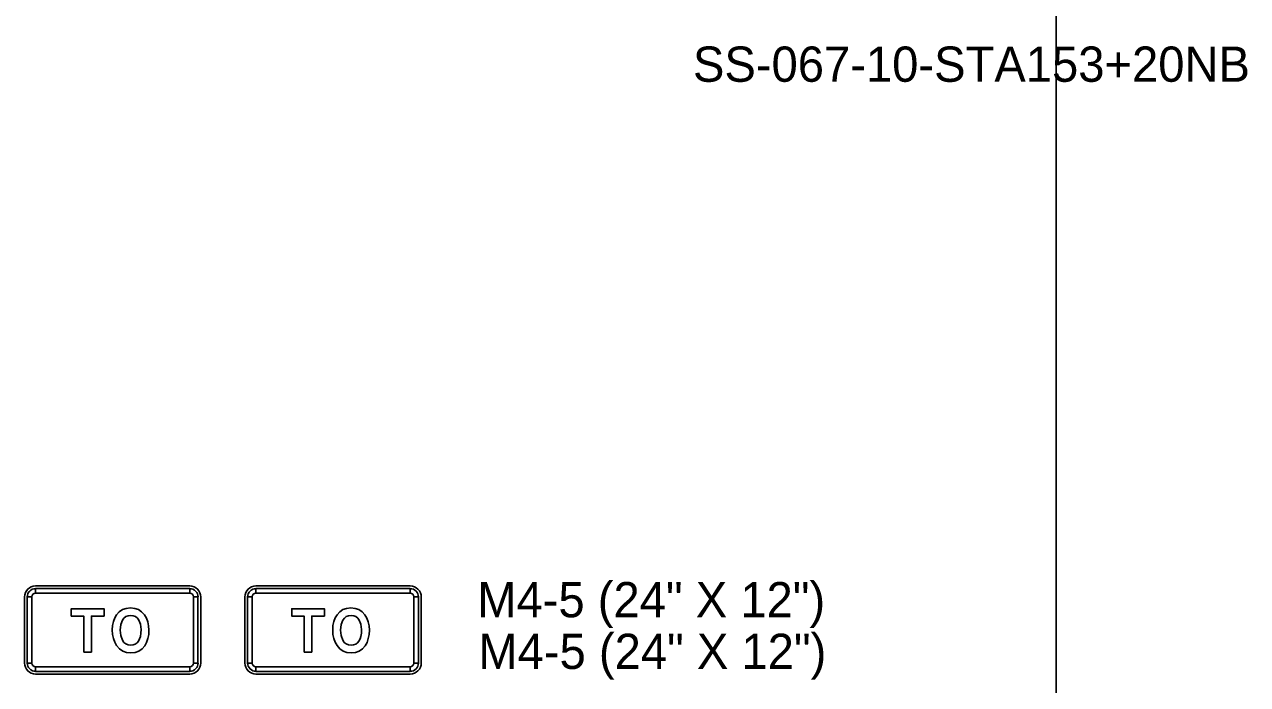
# Model space of a CAD drawing. Extents: x 1001568 to 1002149, y 1840825 to 1841423.
# Drawn here: x 1001938.95 to 1001952.82, y 1841187.33 to 1841194.82 of the extents above; entities that cross this region are included whole.
import ezdxf

# ---------------------------------------------------------------- set-up
doc = ezdxf.new("R2010")
doc.units = 0
for name, color, linetype in [('40', 7, 'Continuous'), ('R_No Plot', 7, 'Continuous'), ('SIGNS', 7, 'Continuous')]:
    doc.layers.add(name, color=color, linetype=linetype)

msp = doc.modelspace()

# ---------------------------------------------------------------- linework, layer by layer
at = {"layer": 'R_No Plot'}
msp.add_line((1001950.65, 1841210.667), (1001950.65, 1841148.127), dxfattribs=at)
at = {"layer": 'SIGNS'}
for p, q in [((1001940.823, 1841188.451), (1001939.073, 1841188.451)), ((1001943.323, 1841188.451), (1001941.573, 1841188.451)), ((1001938.948, 1841188.326), (1001938.948, 1841187.576)), ((1001938.979, 1841188.326), (1001939.031, 1841188.326)), ((1001939.073, 1841188.368), (1001939.073, 1841188.42)), ((1001940.823, 1841188.42), (1001940.823, 1841188.368)), ((1001940.864, 1841188.326), (1001940.916, 1841188.326)), ((1001940.948, 1841187.576), (1001940.948, 1841188.326)), ((1001941.448, 1841188.326), (1001941.448, 1841187.576)), ((1001941.479, 1841188.326), (1001941.531, 1841188.326)), ((1001941.573, 1841188.368), (1001941.573, 1841188.42)), ((1001943.323, 1841188.42), (1001943.323, 1841188.368)), ((1001943.364, 1841188.326), (1001943.416, 1841188.326)), ((1001943.448, 1841187.576), (1001943.448, 1841188.326)), ((1001939.031, 1841187.576), (1001938.979, 1841187.576)), ((1001939.073, 1841187.482), (1001939.073, 1841187.534)), ((1001940.823, 1841187.534), (1001940.823, 1841187.482)), ((1001940.916, 1841187.576), (1001940.864, 1841187.576)), ((1001941.531, 1841187.576), (1001941.479, 1841187.576)), ((1001941.573, 1841187.482), (1001941.573, 1841187.534)), ((1001943.323, 1841187.534), (1001943.323, 1841187.482)), ((1001943.416, 1841187.576), (1001943.364, 1841187.576)), ((1001939.073, 1841187.451), (1001940.823, 1841187.451)), ((1001941.573, 1841187.451), (1001943.323, 1841187.451))]:
    msp.add_line(p, q, dxfattribs=at)
for points in [[(1001938.979, 1841188.326), (1001938.979, 1841187.576), (1001939.031, 1841187.576), (1001939.031, 1841188.326), (1001938.979, 1841188.326), (1001938.979, 1841188.326)], [(1001940.823, 1841188.42), (1001939.073, 1841188.42), (1001939.073, 1841188.368), (1001940.823, 1841188.368), (1001940.823, 1841188.42), (1001940.823, 1841188.42)], [(1001940.916, 1841187.576), (1001940.916, 1841188.326), (1001940.864, 1841188.326), (1001940.864, 1841187.576), (1001940.916, 1841187.576), (1001940.916, 1841187.576)], [(1001941.479, 1841188.326), (1001941.479, 1841187.576), (1001941.531, 1841187.576), (1001941.531, 1841188.326), (1001941.479, 1841188.326), (1001941.479, 1841188.326)], [(1001943.323, 1841188.42), (1001941.573, 1841188.42), (1001941.573, 1841188.368), (1001943.323, 1841188.368), (1001943.323, 1841188.42), (1001943.323, 1841188.42)], [(1001943.416, 1841187.576), (1001943.416, 1841188.326), (1001943.364, 1841188.326), (1001943.364, 1841187.576), (1001943.416, 1841187.576), (1001943.416, 1841187.576)], [(1001939.62, 1841187.701), (1001939.707, 1841187.701), (1001939.707, 1841188.109), (1001939.85, 1841188.109), (1001939.85, 1841188.192), (1001939.479, 1841188.192), (1001939.479, 1841188.109), (1001939.62, 1841188.109)], [(1001942.12, 1841187.701), (1001942.207, 1841187.701), (1001942.207, 1841188.109), (1001942.35, 1841188.109), (1001942.35, 1841188.192), (1001941.979, 1841188.192), (1001941.979, 1841188.109), (1001942.12, 1841188.109)], [(1001939.073, 1841187.482), (1001940.823, 1841187.482), (1001940.823, 1841187.534), (1001939.073, 1841187.534), (1001939.073, 1841187.482), (1001939.073, 1841187.482)], [(1001941.573, 1841187.482), (1001943.323, 1841187.482), (1001943.323, 1841187.534), (1001941.573, 1841187.534), (1001941.573, 1841187.482), (1001941.573, 1841187.482)]]:
    msp.add_lwpolyline(points, close=True, dxfattribs=at)
for points in [[(1001940.36, 1841187.95), (1001940.356, 1841188), (1001940.347, 1841188.045), (1001940.331, 1841188.086), (1001940.309, 1841188.123), (1001940.277, 1841188.157), (1001940.24, 1841188.182), (1001940.198, 1841188.196), (1001940.149, 1841188.201), (1001940.102, 1841188.196), (1001940.06, 1841188.182), (1001940.023, 1841188.157), (1001939.993, 1841188.124), (1001939.971, 1841188.088), (1001939.956, 1841188.047), (1001939.947, 1841188.002), (1001939.944, 1841187.953), (1001939.947, 1841187.901), (1001939.956, 1841187.855), (1001939.972, 1841187.812), (1001939.993, 1841187.774), (1001940.024, 1841187.738), (1001940.062, 1841187.712), (1001940.105, 1841187.697), (1001940.153, 1841187.692), (1001940.202, 1841187.697), (1001940.244, 1841187.712), (1001940.281, 1841187.737), (1001940.312, 1841187.773), (1001940.333, 1841187.811), (1001940.348, 1841187.853), (1001940.357, 1841187.899), (1001940.36, 1841187.95)], [(1001942.86, 1841187.95), (1001942.856, 1841188), (1001942.847, 1841188.045), (1001942.831, 1841188.086), (1001942.809, 1841188.123), (1001942.777, 1841188.157), (1001942.74, 1841188.182), (1001942.698, 1841188.196), (1001942.649, 1841188.201), (1001942.602, 1841188.196), (1001942.56, 1841188.182), (1001942.523, 1841188.157), (1001942.493, 1841188.124), (1001942.471, 1841188.088), (1001942.456, 1841188.047), (1001942.447, 1841188.002), (1001942.444, 1841187.953), (1001942.447, 1841187.901), (1001942.456, 1841187.855), (1001942.472, 1841187.812), (1001942.493, 1841187.774), (1001942.524, 1841187.738), (1001942.562, 1841187.712), (1001942.605, 1841187.697), (1001942.653, 1841187.692), (1001942.702, 1841187.697), (1001942.744, 1841187.712), (1001942.781, 1841187.737), (1001942.812, 1841187.773), (1001942.833, 1841187.811), (1001942.848, 1841187.853), (1001942.857, 1841187.899), (1001942.86, 1841187.95)], [(1001940.271, 1841187.957), (1001940.269, 1841187.915), (1001940.263, 1841187.879), (1001940.254, 1841187.849), (1001940.241, 1841187.824), (1001940.225, 1841187.804), (1001940.205, 1841187.791), (1001940.181, 1841187.782), (1001940.153, 1841187.78), (1001940.123, 1841187.783), (1001940.097, 1841187.794), (1001940.075, 1841187.811), (1001940.058, 1841187.836), (1001940.039, 1841187.887), (1001940.033, 1841187.95), (1001940.039, 1841188.012), (1001940.058, 1841188.062), (1001940.076, 1841188.086), (1001940.098, 1841188.103), (1001940.124, 1841188.113), (1001940.153, 1841188.117), (1001940.182, 1841188.113), (1001940.207, 1841188.103), (1001940.228, 1841188.087), (1001940.245, 1841188.064), (1001940.264, 1841188.016), (1001940.271, 1841187.957)], [(1001942.771, 1841187.957), (1001942.769, 1841187.915), (1001942.763, 1841187.879), (1001942.754, 1841187.849), (1001942.741, 1841187.824), (1001942.725, 1841187.804), (1001942.705, 1841187.791), (1001942.681, 1841187.782), (1001942.653, 1841187.78), (1001942.623, 1841187.783), (1001942.597, 1841187.794), (1001942.575, 1841187.811), (1001942.558, 1841187.836), (1001942.539, 1841187.887), (1001942.533, 1841187.95), (1001942.539, 1841188.012), (1001942.558, 1841188.062), (1001942.576, 1841188.086), (1001942.598, 1841188.103), (1001942.624, 1841188.113), (1001942.653, 1841188.117), (1001942.682, 1841188.113), (1001942.707, 1841188.103), (1001942.728, 1841188.087), (1001942.745, 1841188.064), (1001942.764, 1841188.016), (1001942.771, 1841187.957)]]:
    msp.add_lwpolyline(points, dxfattribs=at)
for centre, radius, start, end in [((1001939.073, 1841188.326), 0.125, 90.0002, 179.9998), ((1001940.823, 1841188.326), 0.125, 360, 90.0002), ((1001941.573, 1841188.326), 0.125, 90.0002, 179.9998), ((1001943.323, 1841188.326), 0.125, 360, 90.0002), ((1001939.073, 1841188.326), 0.0937, 90.0002, 179.9998), ((1001939.073, 1841188.326), 0.0417, 90.0002, 179.9998), ((1001940.823, 1841188.326), 0.0937, 360, 90.0002), ((1001940.823, 1841188.326), 0.0417, 360, 90.0002), ((1001941.573, 1841188.326), 0.0937, 90.0002, 179.9998), ((1001941.573, 1841188.326), 0.0417, 90.0002, 179.9998), ((1001943.323, 1841188.326), 0.0937, 360, 90.0002), ((1001943.323, 1841188.326), 0.0417, 360, 90.0002), ((1001939.073, 1841187.576), 0.125, 179.9998, 270.0001), ((1001939.073, 1841187.576), 0.0937, 179.9998, 270.0001), ((1001939.073, 1841187.576), 0.0417, 179.9998, 270.0001), ((1001940.823, 1841187.576), 0.125, 270.0001, 0.0003), ((1001940.823, 1841187.576), 0.0937, 270.0001, 0.0003), ((1001940.823, 1841187.576), 0.0417, 270.0001, 0.0003), ((1001941.573, 1841187.576), 0.125, 179.9998, 270.0001), ((1001941.573, 1841187.576), 0.0937, 179.9998, 270.0001), ((1001941.573, 1841187.576), 0.0417, 179.9998, 270.0001), ((1001943.323, 1841187.576), 0.125, 270.0001, 0.0003), ((1001943.323, 1841187.576), 0.0937, 270.0001, 0.0003), ((1001943.323, 1841187.576), 0.0417, 270.0001, 0.0003)]:
    msp.add_arc(centre, radius, start, end, dxfattribs=at)

# ---------------------------------------------------------------- texts
at = {"layer": '40'}
for s, p in [('SS-067-10-STA153+20NB', (1001946.53, 1841194.169)), ('M4-5 (24" X 12")', (1001944.083, 1841188.095)), ('M4-5 (24" X 12")', (1001944.096, 1841187.509))]:
    msp.add_text(s, height=0.4, rotation=0, dxfattribs=at).set_placement(p)

doc.saveas('drawing.dxf')
